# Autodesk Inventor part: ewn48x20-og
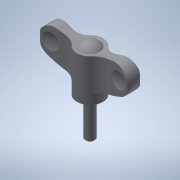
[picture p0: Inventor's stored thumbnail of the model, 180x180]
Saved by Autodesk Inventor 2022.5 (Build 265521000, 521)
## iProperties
Created: 2016-12
Part Number: ewn48x20-og
Material: 一般
Document SubType Name: Modeling
Designer: imaocorp
Density: 1 g/cm^3
Appearance: 既定
Author: imaocorp
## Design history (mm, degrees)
node "ewn48x20-og.x_t1"
node "ewn48x20-og"
node "Base1"
